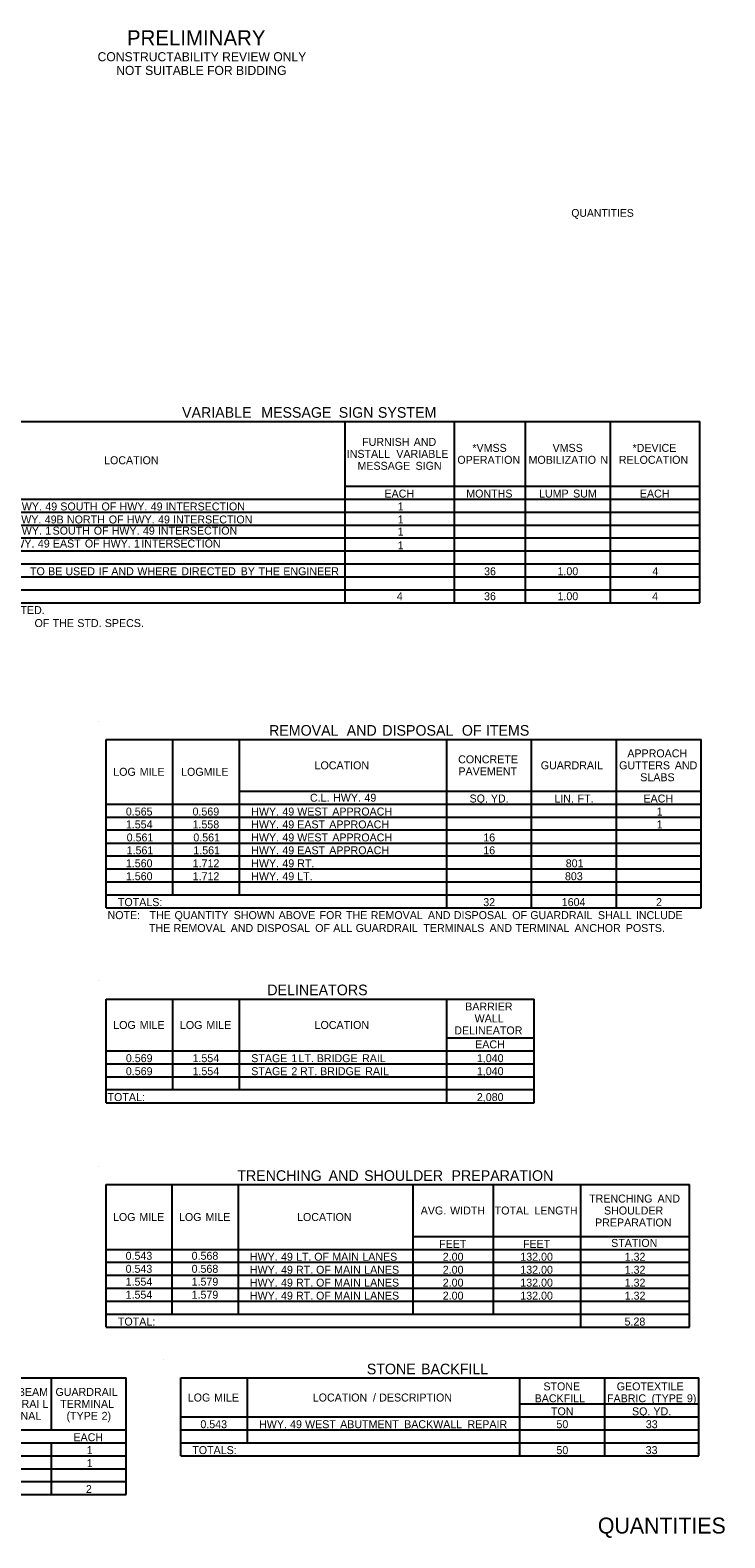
# Model space of a CAD drawing. Extents: x 107 to 7866, y 32 to 1473.
# Drawn here: x 3209 to 3733, y 32 to 1167 of the extents above; entities that cross this region are included whole.
import ezdxf

# ---------------------------------------------------------------- set-up
doc = ezdxf.new("R2010")
doc.units = 0
for name, color, linetype in [('Default', 7, 'Continuous'), ('R_Annotation', 7, 'Continuous'), ('R_Border', 7, 'Continuous'), ('R_Draft', 7, 'Continuous')]:
    doc.layers.add(name, color=color, linetype=linetype)

msp = doc.modelspace()

# ---------------------------------------------------------------- linework, layer by layer
at = {"layer": 'Default'}
for p, q in [((3126.7, 872.1), (3713.7, 872.1)), ((3446.5, 735.6), (3446.5, 872.1)), ((3528.9, 735.6), (3528.9, 872.1)), ((3582.5, 735.6), (3582.5, 872.1)), ((3646.4, 735.6), (3646.4, 872.1)), ((3713.7, 735.6), (3713.7, 872.1)), ((3713.7, 735.6), (3713.7, 872.1)), ((3446.5, 823.4), (3713.7, 823.4)), ((3126.7, 813.6), (3713.7, 813.6)), ((3446.5, 745.4), (3446.5, 813.6)), ((3528.9, 794.1), (3528.9, 813.6)), ((3126.7, 803.9), (3713.7, 803.9)), ((3126.7, 794.1), (3713.7, 794.1)), ((3126.7, 784.4), (3713.7, 784.4)), ((3528.9, 735.6), (3528.9, 784.4)), ((3126.7, 774.6), (3713.7, 774.6)), ((3126.7, 764.9), (3713.7, 764.9)), ((3126.7, 755.1), (3713.7, 755.1)), ((3126.7, 745.4), (3713.7, 745.4)), ((3528.9, 745.4), (3713.7, 745.4)), ((3582.5, 735.6), (3582.5, 745.4)), ((3646.4, 735.6), (3646.4, 745.4)), ((3126.7, 735.6), (3713.7, 735.6)), ((3260.9, 646.4), (3260.9, 646.4)), ((3266.7, 632.7), (3714.7, 632.7)), ((3266.7, 506), (3266.7, 632.7)), ((3266.7, 506), (3266.7, 632.7)), ((3316.9, 515.7), (3316.9, 632.7)), ((3367.1, 515.7), (3367.1, 632.7)), ((3523.1, 506), (3523.1, 632.7)), ((3587, 506), (3587, 632.7)), ((3650.9, 506), (3650.9, 632.7)), ((3714.7, 506), (3714.7, 632.7)), ((3367.1, 593.7), (3523.1, 593.7)), ((3367.1, 593.7), (3714.7, 593.7)), ((3266.7, 584), (3714.7, 584)), ((3316.9, 515.7), (3316.9, 584)), ((3367.1, 584), (3523.1, 584)), ((3367.1, 515.7), (3367.1, 584)), ((3523.1, 564.5), (3523.1, 584)), ((3587, 506), (3587, 584)), ((3650.9, 584), (3714.7, 584)), ((3266.7, 574.2), (3714.7, 574.2)), ((3367.1, 574.2), (3523.1, 574.2)), ((3523.1, 574.2), (3650.9, 574.2)), ((3650.9, 574.2), (3714.7, 574.2)), ((3266.7, 564.5), (3714.7, 564.5)), ((3367.1, 564.5), (3523.1, 564.5)), ((3523.1, 564.5), (3650.9, 564.5)), ((3650.9, 564.5), (3714.7, 564.5)), ((3266.7, 554.7), (3714.7, 554.7)), ((3266.7, 545), (3714.7, 545)), ((3523.1, 506), (3523.1, 554.7)), ((3266.7, 535.2), (3714.7, 535.2)), ((3266.7, 525.5), (3714.7, 525.5)), ((3266.7, 515.7), (3714.7, 515.7)), ((3587, 515.7), (3650.9, 515.7)), ((3650.9, 515.7), (3714.7, 515.7)), ((3266.7, 506), (3714.7, 506)), ((3260.9, 450.9), (3260.9, 450.9)), ((3266.7, 437.2), (3588.9, 437.2)), ((3266.7, 359.2), (3266.7, 437.2)), ((3266.7, 359.2), (3266.7, 437.2)), ((3316.9, 369), (3316.9, 437.2)), ((3367.1, 369), (3367.1, 437.2)), ((3523.1, 359.2), (3523.1, 437.2)), ((3588.9, 359.2), (3588.9, 437.2)), ((3588.9, 359.2), (3588.9, 437.2)), ((3266.7, 398.2), (3588.9, 398.2)), ((3367.1, 369), (3367.1, 398.2)), ((3523.1, 408), (3588.9, 408)), ((3523.1, 369), (3523.1, 398.2)), ((3266.7, 388.5), (3588.9, 388.5)), ((3316.9, 369), (3316.9, 388.5)), ((3523.1, 388.5), (3588.9, 388.5)), ((3266.7, 378.7), (3588.9, 378.7)), ((3266.7, 369), (3588.9, 369)), ((3266.7, 359.2), (3588.9, 359.2)), ((3260.9, 311.1), (3260.9, 311.1)), ((3266.7, 297.5), (3705.9, 297.5)), ((3266.7, 190.2), (3266.7, 297.5)), ((3266.7, 190.2), (3266.7, 297.5)), ((3316.4, 200), (3316.4, 297.5)), ((3366.2, 200), (3366.2, 297.5)), ((3497.8, 200), (3497.8, 297.5)), ((3558.2, 200), (3558.2, 297.5)), ((3624, 190.2), (3624, 297.5)), ((3705.9, 190.2), (3705.9, 297.5)), ((3705.9, 190.2), (3705.9, 297.5)), ((3497.8, 258.5), (3705.9, 258.5)), ((3497.8, 200), (3497.8, 258.5)), ((3558.2, 248.7), (3558.2, 258.5)), ((3266.7, 248.7), (3705.9, 248.7)), ((3266.7, 239), (3705.9, 239)), ((3316.4, 200), (3316.4, 248.7)), ((3366.2, 200), (3366.2, 248.7)), ((3624, 200), (3624, 248.7)), ((3266.7, 229.2), (3705.9, 229.2)), ((3266.7, 219.5), (3705.9, 219.5)), ((3266.7, 209.7), (3705.9, 209.7)), ((3266.7, 200), (3316.4, 200)), ((3266.7, 200), (3705.9, 200)), ((3316.4, 200), (3366.2, 200)), ((3366.2, 200), (3497.8, 200)), ((3497.8, 200), (3558.2, 200)), ((3558.2, 200), (3705.9, 200)), ((3266.7, 190.2), (3705.9, 190.2)), ((3309.6, 165.5), (3309.6, 165.5)), ((2861.4, 151.9), (3281.6, 151.9)), ((3225.5, 112.9), (3225.5, 151.9)), ((3281.6, 64.1), (3281.6, 151.9)), ((3322.8, 151.9), (3712.8, 151.9)), ((3322.8, 93.4), (3322.8, 151.9)), ((3322.8, 93.4), (3322.8, 151.9)), ((3373, 103.1), (3373, 151.9)), ((3578.2, 93.4), (3578.2, 151.9)), ((3642.1, 93.4), (3642.1, 151.9)), ((3712.8, 93.4), (3712.8, 151.9)), ((3578.2, 132.4), (3712.8, 132.4)), ((3322.8, 122.6), (3712.8, 122.6)), ((3373, 103.1), (3373, 122.6)), ((3578.2, 103.1), (3578.2, 122.6)), ((2861.4, 103.1), (3281.6, 103.1)), ((2960.8, 112.9), (3281.6, 112.9)), ((3225.5, 64.1), (3225.5, 103.1)), ((3225.5, 64.1), (3225.5, 103.1)), ((3281.6, 64.1), (3281.6, 112.9)), ((3322.8, 112.9), (3712.8, 112.9)), ((3322.8, 103.1), (3712.8, 103.1)), ((2861.4, 93.4), (3281.6, 93.4)), ((3322.8, 93.4), (3712.8, 93.4)), ((2861.4, 83.6), (3281.6, 83.6)), ((2861.4, 73.9), (3281.6, 73.9)), ((2861.4, 64.1), (3281.6, 64.1))]:
    msp.add_line(p, q, dxfattribs=at)

# ---------------------------------------------------------------- texts
for s, height, p in [('VARIABLE', 8, (3323.8, 874.9)), (' MESSAGE', 8, (3380.4, 874.9)), (' SIGN', 8, (3438.8, 874.9)), (' SYSTEM', 8, (3468.3, 874.9)), ('FURNISH', 6, (3459.4, 853.7)), (' AND', 6, (3496, 853.7)), ('*VMSS', 6, (3542.4, 849.2)), ('VMSS', 6, (3602.8, 849.2)), ('*DEVICE', 6, (3663, 849.2)), ('LOCATION', 6, (3265.1, 839.9)), ('INSTALL', 6, (3447.8, 844.7)), ('MESSAGE', 6, (3455.9, 835.7)), (' VARIABLE', 6, (3482.9, 844.7)), (' SIGN', 6, (3497.4, 835.7)), ('OPERATION', 6, (3531.1, 840.2)), ('MOBILIZATIO', 6, (3584.7, 840.2)), ('N', 6, (3638.8, 840.2)), ('RELOCATION', 6, (3652.7, 840.2)), ('EACH', 6, (3476.2, 814.8)), ('MONTHS', 6, (3537.8, 814.8)), ('LUMP', 6, (3592.6, 814.8)), (' SUM', 6, (3616, 814.8)), ('EACH', 6, (3668.5, 814.8)), (' HWY.', 6, (3195.1, 805.1)), (' 49', 6, (3218.6, 805.1)), (' SOUTH', 6, (3229.9, 805.1)), (' OF', 6, (3260.9, 805.1)), (' HWY.', 6, (3274.5, 805.1)), (' 49', 6, (3298, 805.1)), (' INTERSECTION', 6, (3309.2, 805.1)), ('1', 6, (3486.2, 805.1)), (' HWY.', 6, (3194.7, 795.3)), (' 49B', 6, (3218.2, 795.3)), (' NORTH', 6, (3234.9, 795.3)), (' OF', 6, (3266.4, 795.3)), (' HWY.', 6, (3280, 795.3)), (' 49', 6, (3303.5, 795.3)), (' INTERSECTION', 6, (3314.8, 795.3)), ('1', 6, (3486.2, 795.3)), (' HWY.', 6, (3195.1, 786.9)), (' 1', 6, (3218.6, 786.9)), (' SOUTH', 6, (3224.1, 786.9)), (' OF', 6, (3255.1, 786.9)), (' HWY.', 6, (3268.6, 786.9)), (' 49', 6, (3292.1, 786.9)), (' INTERSECTION', 6, (3303.4, 786.9)), ('1', 6, (3486.2, 786.2)), (' HWY.', 6, (3189.5, 777.2)), (' 49', 6, (3213, 777.2)), (' EAST', 6, (3224.3, 777.2)), (' OF', 6, (3248.4, 777.2)), (' HWY.', 6, (3262, 777.2)), (' 1', 6, (3285.4, 777.2)), (' INTERSECTION', 6, (3290.9, 777.2)), ('1', 6, (3486.2, 775.8)), (' TO', 6, (3207.1, 756.3)), (' BE', 6, (3220.7, 756.3)), (' USED', 6, (3233.7, 756.3)), (' IF', 6, (3258.9, 756.3)), (' AND', 6, (3268.3, 756.3)), (' WHERE', 6, (3287.9, 756.3)), (' DIRECTED', 6, (3321, 756.3)), (' BY', 6, (3365.7, 756.3)), (' THE', 6, (3379.2, 756.3)), (' ENGINEER', 6, (3397.8, 756.3)), ('36', 6, (3551.2, 756.3)), ('1.00', 6, (3606.5, 756.3)), ('4', 6, (3677.9, 756.3)), ('4', 6, (3485.5, 737.5)), ('36', 6, (3551.2, 737.5)), ('1.00', 6, (3606.5, 737.5)), ('4', 6, (3677.8, 737.5)), (' ESTIMATED.', 6, (3170, 727.1)), (' OF', 6, (3210.5, 717.3)), (' THE', 6, (3224.1, 717.3)), (' STD.', 6, (3242.7, 717.3)), (' SPECS.', 6, (3263.4, 717.3)), ('REMOVAL', 8, (3389.3, 635.5)), (' AND', 8, (3444.8, 635.5)), (' DISPOSAL', 8, (3471.6, 635.5)), (' OF', 8, (3531.5, 635.5)), (' ITEMS', 8, (3549.6, 635.5)), ('APPROACH', 6, (3659.1, 619.2)), ('LOCATION', 6, (3423.6, 610.2)), ('CONCRETE', 6, (3531.7, 614.7)), ('GUARDRAIL', 6, (3593.9, 610.2)), ('GUTTERS', 6, (3652.9, 610.2)), (' AND', 6, (3692.6, 610.2)), ('LOG', 6, (3272, 605.3)), (' MILE', 6, (3289.7, 605.3)), ('LOGMILE', 6, (3323.1, 605.3)), ('PAVEMENT', 6, (3531.9, 605.7)), ('SLABS', 6, (3668.8, 601.2)), ('C.L.', 6, (3420.1, 585.8)), (' HWY.', 6, (3435.3, 585.8)), (' 49', 6, (3458.9, 585.8)), ('SQ.', 6, (3540.3, 585.2)), (' YD.', 6, (3554.1, 585.2)), ('LIN.', 6, (3604.1, 585.2)), (' FT.', 6, (3619.4, 585.2)), ('EACH', 6, (3671.2, 585.2)), ('0.565', 6, (3281.5, 575.4)), ('0.569', 6, (3331.7, 575.4)), ('HWY.', 6, (3375.9, 575.4)), (' 49', 6, (3397.1, 575.4)), (' WEST', 6, (3408.3, 575.4)), (' APPROACH', 6, (3434.7, 575.4)), ('1', 6, (3681.2, 575.4)), ('1.554', 6, (3281.5, 565.7)), ('1.558', 6, (3331.7, 565.7)), ('HWY.', 6, (3375.9, 565.7)), (' 49', 6, (3397.1, 565.7)), (' EAST', 6, (3408.3, 565.7)), (' APPROACH', 6, (3432.4, 565.7)), ('1', 6, (3681.2, 565.7)), ('0.561', 6, (3282.1, 555.9)), ('0.561', 6, (3332.3, 555.9)), ('HWY.', 6, (3375.9, 555.9)), (' 49', 6, (3397.1, 555.9)), (' WEST', 6, (3408.3, 555.9)), (' APPROACH', 6, (3434.7, 555.9)), ('16', 6, (3550.6, 555.9)), ('1.561', 6, (3282.1, 546.2)), ('1.561', 6, (3332.3, 546.2)), ('HWY.', 6, (3375.9, 546.2)), (' 49', 6, (3397.1, 546.2)), (' EAST', 6, (3408.3, 546.2)), (' APPROACH', 6, (3432.4, 546.2)), ('16', 6, (3550.6, 546.2)), ('1.560', 6, (3281.5, 536.4)), ('1.712', 6, (3331.8, 536.4)), ('HWY.', 6, (3375.9, 536.4)), (' 49', 6, (3397.1, 536.4)), (' RT.', 6, (3408.3, 536.4)), ('801', 6, (3612.7, 536.4)), ('1.560', 6, (3281.5, 526.7)), ('1.712', 6, (3331.8, 526.7)), ('HWY.', 6, (3375.9, 526.7)), (' 49', 6, (3397.1, 526.7)), (' LT.', 6, (3408.3, 526.7)), ('803', 6, (3612.1, 526.7)), ('TOTALS:', 6, (3275.5, 507.2)), ('32', 6, (3550.6, 507.2)), ('1604', 6, (3609.7, 507.2)), ('2', 6, (3680.7, 507.2)), ('NOTE:', 6, (3267.7, 497.4)), ('   THE', 6, (3292.6, 497.4)), (' QUANTITY', 6, (3315.9, 497.4)), (' SHOWN', 6, (3360.5, 497.4)), (' ABOVE', 6, (3394.3, 497.4)), (' FOR', 6, (3425.1, 497.4)), (' THE', 6, (3445, 497.4)), (' REMOVAL', 6, (3463.6, 497.4)), (' AND', 6, (3506.7, 497.4)), (' DISPOSAL', 6, (3526.2, 497.4)), (' OF', 6, (3570.2, 497.4)), (' GUARDRAIL', 6, (3583.8, 497.4)), (' SHALL', 6, (3634.7, 497.4)), (' INCLUDE', 6, (3663.3, 497.4)), ('THE', 6, (3298.9, 487.7)), (' REMOVAL', 6, (3315.2, 487.7)), (' AND', 6, (3358.2, 487.7)), (' DISPOSAL', 6, (3377.8, 487.7)), (' OF', 6, (3421.8, 487.7)), (' ALL', 6, (3435.4, 487.7)), (' GUARDRAIL', 6, (3452.3, 487.7)), (' TERMINALS', 6, (3503.3, 487.7)), (' AND', 6, (3553.1, 487.7)), (' TERMINAL', 6, (3572.7, 487.7)), (' ANCHOR', 6, (3617.1, 487.7)), (' POSTS.', 6, (3655.7, 487.7)), ('DELINEATORS', 8, (3388, 440.1)), ('BARRIER', 6, (3537, 428.6)), ('LOG', 6, (3272, 414.7)), (' MILE', 6, (3289.7, 414.7)), ('LOG', 6, (3322.2, 414.7)), (' MILE', 6, (3339.9, 414.7)), ('LOCATION', 6, (3423.6, 414.7)), ('WALL', 6, (3544.1, 419.6)), ('DELINEATOR', 6, (3528.8, 410.6)), ('EACH', 6, (3544.5, 400.1)), ('0.569', 6, (3281.5, 389.7)), ('0.569', 6, (3281.5, 379.9)), ('1.554', 6, (3331.7, 389.7)), ('STAGE', 6, (3375.9, 389.7)), ('STAGE', 6, (3375.9, 379.9)), (' 2', 6, (3403.9, 379.9)), (' 1', 6, (3403.9, 389.7)), (' LT.', 6, (3409.3, 389.7)), (' BRIDGE', 6, (3423, 389.7)), (' BRIDGE', 6, (3425.5, 379.9)), (' RAIL', 6, (3457.1, 389.7)), ('1,040', 6, (3545.8, 389.7)), ('1,040', 6, (3545.8, 379.9)), ('1.554', 6, (3331.7, 379.9)), (' RT.', 6, (3410.4, 379.9)), (' RAIL', 6, (3459.5, 379.9)), ('TOTAL:', 6, (3267.7, 360.4)), ('2,080', 6, (3545.8, 360.4)), ('TRENCHING', 8, (3365.4, 300.3)), (' AND', 8, (3431.2, 300.3)), (' SHOULDER', 8, (3457.9, 300.3)), (' PREPARATION', 8, (3523.7, 300.3)), ('TRENCHING', 6, (3630.3, 284)), (' AND', 6, (3679.6, 284)), ('LOG', 6, (3271.8, 270.1)), (' MILE', 6, (3289.4, 270.1)), ('LOG', 6, (3321.5, 270.1)), (' MILE', 6, (3339.2, 270.1)), ('LOCATION', 6, (3410.4, 270.1)), ('AVG.', 6, (3503.5, 275)), (' WIDTH', 6, (3523.4, 275)), ('TOTAL', 6, (3559.2, 275)), (' LENGTH', 6, (3586.9, 275)), ('SHOULDER', 6, (3641.5, 275)), ('PREPARATION', 6, (3634.8, 266)), ('FEET', 6, (3517.4, 249.9)), ('FEET', 6, (3580.5, 249.9)), ('STATION', 6, (3646.9, 250.6)), ('0.543', 6, (3281.3, 240.9)), ('0.568', 6, (3331, 240.9)), ('HWY.', 6, (3374.9, 240.2)), (' 49', 6, (3396.1, 240.2)), (' LT.', 6, (3407.4, 240.2)), (' OF', 6, (3421.1, 240.2)), (' MAIN', 6, (3434.7, 240.2)), (' LANES', 6, (3457.3, 240.2)), ('2.00', 6, (3520.1, 240.2)), ('132.00', 6, (3578.5, 240.2)), ('1.32', 6, (3657.1, 240.2)), ('0.543', 6, (3281.3, 231.1)), ('1.554', 6, (3281.3, 221.4)), ('0.568', 6, (3331, 231.1)), ('1.579', 6, (3331, 221.4)), ('HWY.', 6, (3374.9, 230.4)), (' 49', 6, (3396.1, 230.4)), (' RT.', 6, (3407.4, 230.4)), (' OF', 6, (3422.5, 230.4)), (' MAIN', 6, (3436.1, 230.4)), (' LANES', 6, (3458.7, 230.4)), ('2.00', 6, (3520.1, 230.4)), ('132.00', 6, (3578.5, 230.4)), ('1.32', 6, (3657.1, 230.4)), ('1.554', 6, (3281.3, 211.6)), ('1.579', 6, (3331, 211.6)), ('HWY.', 6, (3374.9, 220.7)), ('HWY.', 6, (3374.9, 210.9)), (' 49', 6, (3396.1, 220.7)), (' 49', 6, (3396.1, 210.9)), (' RT.', 6, (3407.4, 220.7)), (' RT.', 6, (3407.4, 210.9)), (' OF', 6, (3422.5, 220.7)), (' OF', 6, (3422.5, 210.9)), (' MAIN', 6, (3436.1, 220.7)), (' MAIN', 6, (3436.1, 210.9)), (' LANES', 6, (3458.7, 220.7)), (' LANES', 6, (3458.7, 210.9)), ('2.00', 6, (3520.1, 220.7)), ('2.00', 6, (3520.1, 210.9)), ('132.00', 6, (3578.5, 220.7)), ('132.00', 6, (3578.5, 210.9)), ('1.32', 6, (3657.1, 220.7)), ('1.32', 6, (3657.1, 210.9)), ('TOTAL:', 6, (3275.5, 191.4)), ('5.28', 6, (3657, 191.4)), ('STONE', 8, (3462.9, 154.7)), (' BACKFILL', 8, (3500.8, 154.7)), ('STONE', 6, (3595.9, 142.6)), ('GEOTEXTILE', 6, (3651.1, 142.6)), (' BEAM', 6, (3197.9, 138.4)), ('GUARDRAIL', 6, (3228.5, 138.4)), ('LOG', 6, (3328.1, 134.2)), (' MILE', 6, (3345.7, 134.2)), ('LOCATION', 6, (3422.2, 134.2)), (' /', 6, (3465.3, 134.2)), (' DESCRIPTION', 6, (3470, 134.2)), ('BACKFILL', 6, (3589.3, 133.6)), ('FABRIC', 6, (3643.8, 133.6)), (' (TYPE', 6, (3675.1, 133.6)), (' 9)', 6, (3701.7, 133.6)), ('GUARDRAI', 6, (3174, 129.4)), ('TERMINAL', 6, (3177.2, 120.4)), ('L', 6, (3218.6, 129.4)), ('TERMINAL', 6, (3232, 129.4)), ('(TYPE', 6, (3236.8, 120.4)), (' 2)', 6, (3261, 120.4)), ('TON', 6, (3601.6, 123.8)), ('SQ.', 6, (3662.6, 123.8)), (' YD.', 6, (3676.5, 123.8)), ('0.543', 6, (3337.6, 114.1)), ('HWY.', 6, (3381.8, 114.1)), (' 49', 6, (3402.9, 114.1)), (' WEST', 6, (3414.2, 114.1)), (' ABUTMENT', 6, (3440.6, 114.1)), (' BACKWALL', 6, (3488.8, 114.1)), (' REPAIR', 6, (3536.5, 114.1)), ('50', 6, (3605.7, 114.1)), ('33', 6, (3673, 114.1)), ('EACH', 6, (3242, 104.3)), ('1', 6, (3252, 94.6)), ('1', 6, (3252, 84.8)), ('TOTALS:', 6, (3331.5, 94.6)), ('50', 6, (3605.7, 94.6)), ('33', 6, (3672.9, 94.6)), ('2', 6, (3251.4, 65.3))]:
    msp.add_text(s, height=height, dxfattribs=at).set_placement(p)
at = {"layer": 'R_Annotation'}
msp.add_text('QUANTITIES', height=12, rotation=360, dxfattribs=at).set_placement((3636.9, 34.8))
at = {"layer": 'R_Border'}
msp.add_text('QUANTITIES', height=5.86, dxfattribs=at).set_placement((3616.9, 1026.2))
at = {"layer": 'R_Draft'}
for s, height, p in [('PRELIMINARY', 11.508, (3282.3, 1155.2)), ('CONSTRUCTABILITY REVIEW ONLY', 6.823, (3260.2, 1143.3)), ('NOT SUITABLE FOR BIDDING', 6.823, (3274.2, 1133))]:
    msp.add_text(s, height=height, rotation=0, dxfattribs=at).set_placement(p)

doc.saveas('drawing.dxf')
